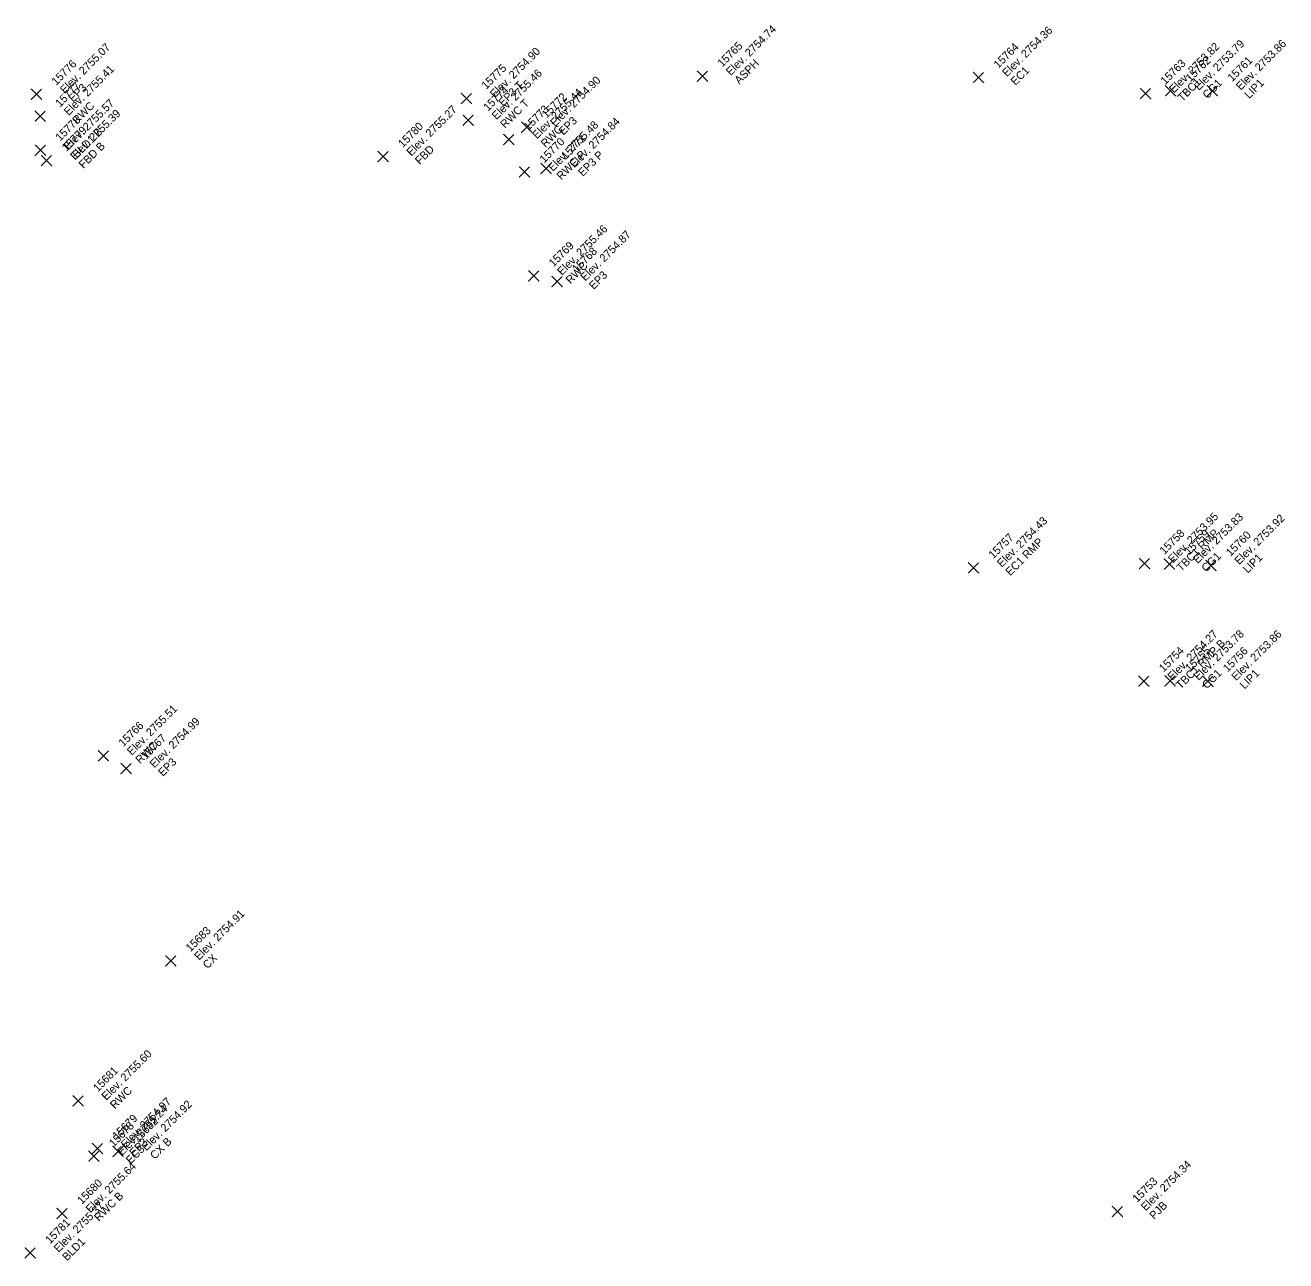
# Model space of a CAD drawing. Extents: x 2493999 to 2503109, y 700767 to 706646.
# Drawn here: x 2502227.16 to 2502264.97, y 704078.66 to 704115.72 of the extents above; entities that cross this region are included whole.
import ezdxf

# ---------------------------------------------------------------- set-up
doc = ezdxf.new("R2010")
doc.units = 0
doc.layers.add('ALG_CL_BLUE_Horiz', color=7, linetype='Continuous')
doc.layers.add('DES_SURFACE_Existing-Ground', color=7, linetype='Continuous')

msp = doc.modelspace()

# ---------------------------------------------------------------- linework, layer by layer
at = {"layer": 'ALG_CL_BLUE_Horiz'}
for points in [[(2502247.476, 704114.191), (2502247.326, 704114.341), (2502247.476, 704114.191), (2502247.326, 704114.041), (2502247.476, 704114.191), (2502247.626, 704114.041), (2502247.476, 704114.191), (2502247.626, 704114.341)], [(2502255.76, 704114.155), (2502255.61, 704114.305), (2502255.76, 704114.155), (2502255.61, 704114.005), (2502255.76, 704114.155), (2502255.91, 704114.005), (2502255.76, 704114.155), (2502255.91, 704114.305)], [(2502227.499, 704113.649), (2502227.349, 704113.799), (2502227.499, 704113.649), (2502227.349, 704113.499), (2502227.499, 704113.649), (2502227.649, 704113.499), (2502227.499, 704113.649), (2502227.649, 704113.799)], [(2502240.395, 704113.524), (2502240.245, 704113.674), (2502240.395, 704113.524), (2502240.245, 704113.374), (2502240.395, 704113.524), (2502240.545, 704113.374), (2502240.395, 704113.524), (2502240.545, 704113.674)], [(2502260.767, 704113.667), (2502260.617, 704113.817), (2502260.767, 704113.667), (2502260.617, 704113.517), (2502260.767, 704113.667), (2502260.917, 704113.517), (2502260.767, 704113.667), (2502260.917, 704113.817)], [(2502261.517, 704113.752), (2502261.367, 704113.902), (2502261.517, 704113.752), (2502261.367, 704113.602), (2502261.517, 704113.752), (2502261.667, 704113.602), (2502261.517, 704113.752), (2502261.667, 704113.902)], [(2502262.772, 704113.755), (2502262.622, 704113.905), (2502262.772, 704113.755), (2502262.622, 704113.605), (2502262.772, 704113.755), (2502262.922, 704113.605), (2502262.772, 704113.755), (2502262.922, 704113.905)], [(2502227.614, 704112.994), (2502227.464, 704113.144), (2502227.614, 704112.994), (2502227.464, 704112.844), (2502227.614, 704112.994), (2502227.764, 704112.844), (2502227.614, 704112.994), (2502227.764, 704113.144)], [(2502240.45, 704112.869), (2502240.3, 704113.019), (2502240.45, 704112.869), (2502240.3, 704112.719), (2502240.45, 704112.869), (2502240.6, 704112.719), (2502240.45, 704112.869), (2502240.6, 704113.019)], [(2502242.205, 704112.66), (2502242.055, 704112.81), (2502242.205, 704112.66), (2502242.055, 704112.51), (2502242.205, 704112.66), (2502242.355, 704112.51), (2502242.205, 704112.66), (2502242.355, 704112.81)], [(2502227.616, 704111.968), (2502227.466, 704112.118), (2502227.616, 704111.968), (2502227.466, 704111.818), (2502227.616, 704111.968), (2502227.766, 704111.818), (2502227.616, 704111.968), (2502227.766, 704112.118)], [(2502241.664, 704112.292), (2502241.514, 704112.442), (2502241.664, 704112.292), (2502241.514, 704112.142), (2502241.664, 704112.292), (2502241.814, 704112.142), (2502241.664, 704112.292), (2502241.814, 704112.442)], [(2502227.805, 704111.661), (2502227.655, 704111.811), (2502227.805, 704111.661), (2502227.655, 704111.511), (2502227.805, 704111.661), (2502227.955, 704111.511), (2502227.805, 704111.661), (2502227.955, 704111.811)], [(2502237.896, 704111.779), (2502237.746, 704111.929), (2502237.896, 704111.779), (2502237.746, 704111.629), (2502237.896, 704111.779), (2502238.046, 704111.629), (2502237.896, 704111.779), (2502238.046, 704111.929)], [(2502242.139, 704111.318), (2502241.989, 704111.468), (2502242.139, 704111.318), (2502241.989, 704111.168), (2502242.139, 704111.318), (2502242.289, 704111.168), (2502242.139, 704111.318), (2502242.289, 704111.468)], [(2502242.786, 704111.42), (2502242.636, 704111.57), (2502242.786, 704111.42), (2502242.636, 704111.27), (2502242.786, 704111.42), (2502242.936, 704111.27), (2502242.786, 704111.42), (2502242.936, 704111.57)], [(2502242.415, 704108.2), (2502242.265, 704108.35), (2502242.415, 704108.2), (2502242.265, 704108.05), (2502242.415, 704108.2), (2502242.565, 704108.05), (2502242.415, 704108.2), (2502242.565, 704108.35)], [(2502243.114, 704108.03), (2502242.964, 704108.18), (2502243.114, 704108.03), (2502242.964, 704107.88), (2502243.114, 704108.03), (2502243.264, 704107.88), (2502243.114, 704108.03), (2502243.264, 704108.18)], [(2502260.736, 704099.574), (2502260.586, 704099.724), (2502260.736, 704099.574), (2502260.586, 704099.424), (2502260.736, 704099.574), (2502260.886, 704099.424), (2502260.736, 704099.574), (2502260.886, 704099.724)], [(2502261.483, 704099.559), (2502261.333, 704099.709), (2502261.483, 704099.559), (2502261.333, 704099.409), (2502261.483, 704099.559), (2502261.633, 704099.409), (2502261.483, 704099.559), (2502261.633, 704099.709)], [(2502262.727, 704099.519), (2502262.577, 704099.669), (2502262.727, 704099.519), (2502262.577, 704099.369), (2502262.727, 704099.519), (2502262.877, 704099.369), (2502262.727, 704099.519), (2502262.877, 704099.669)], [(2502255.607, 704099.446), (2502255.457, 704099.596), (2502255.607, 704099.446), (2502255.457, 704099.296), (2502255.607, 704099.446), (2502255.757, 704099.296), (2502255.607, 704099.446), (2502255.757, 704099.596)], [(2502260.718, 704096.048), (2502260.568, 704096.198), (2502260.718, 704096.048), (2502260.568, 704095.898), (2502260.718, 704096.048), (2502260.868, 704095.898), (2502260.718, 704096.048), (2502260.868, 704096.198)], [(2502261.504, 704096.053), (2502261.354, 704096.203), (2502261.504, 704096.053), (2502261.354, 704095.903), (2502261.504, 704096.053), (2502261.654, 704095.903), (2502261.504, 704096.053), (2502261.654, 704096.203)], [(2502262.636, 704096.046), (2502262.486, 704096.196), (2502262.636, 704096.046), (2502262.486, 704095.896), (2502262.636, 704096.046), (2502262.786, 704095.896), (2502262.636, 704096.046), (2502262.786, 704096.196)], [(2502229.509, 704093.807), (2502229.359, 704093.957), (2502229.509, 704093.807), (2502229.359, 704093.657), (2502229.509, 704093.807), (2502229.659, 704093.657), (2502229.509, 704093.807), (2502229.659, 704093.957)], [(2502230.188, 704093.426), (2502230.038, 704093.576), (2502230.188, 704093.426), (2502230.038, 704093.276), (2502230.188, 704093.426), (2502230.338, 704093.276), (2502230.188, 704093.426), (2502230.338, 704093.576)], [(2502231.527, 704087.658), (2502231.377, 704087.808), (2502231.527, 704087.658), (2502231.377, 704087.508), (2502231.527, 704087.658), (2502231.677, 704087.508), (2502231.527, 704087.658), (2502231.677, 704087.808)], [(2502228.746, 704083.457), (2502228.596, 704083.607), (2502228.746, 704083.457), (2502228.596, 704083.307), (2502228.746, 704083.457), (2502228.896, 704083.307), (2502228.746, 704083.457), (2502228.896, 704083.607)], [(2502229.221, 704081.802), (2502229.071, 704081.952), (2502229.221, 704081.802), (2502229.071, 704081.652), (2502229.221, 704081.802), (2502229.371, 704081.652), (2502229.221, 704081.802), (2502229.371, 704081.952)], [(2502229.326, 704082.025), (2502229.176, 704082.175), (2502229.326, 704082.025), (2502229.176, 704081.875), (2502229.326, 704082.025), (2502229.476, 704081.875), (2502229.326, 704082.025), (2502229.476, 704082.175)], [(2502229.946, 704081.943), (2502229.796, 704082.093), (2502229.946, 704081.943), (2502229.796, 704081.793), (2502229.946, 704081.943), (2502230.096, 704081.793), (2502229.946, 704081.943), (2502230.096, 704082.093)], [(2502228.27, 704080.084), (2502228.12, 704080.234), (2502228.27, 704080.084), (2502228.12, 704079.934), (2502228.27, 704080.084), (2502228.42, 704079.934), (2502228.27, 704080.084), (2502228.42, 704080.234)], [(2502259.923, 704080.14), (2502259.773, 704080.29), (2502259.923, 704080.14), (2502259.773, 704079.99), (2502259.923, 704080.14), (2502260.073, 704079.99), (2502259.923, 704080.14), (2502260.073, 704080.29)], [(2502227.312, 704078.898), (2502227.162, 704079.048), (2502227.312, 704078.898), (2502227.162, 704078.748), (2502227.312, 704078.898), (2502227.462, 704078.748), (2502227.312, 704078.898), (2502227.462, 704079.048)]]:
    msp.add_lwpolyline(points, dxfattribs=at)

# ---------------------------------------------------------------- texts
at = {"layer": 'DES_SURFACE_Existing-Ground'}
for s, p in [('Elev. 2754.74', (2502248.325, 704114.191)), ('Elev. 2754.36', (2502256.609, 704114.155)), ('Elev. 2755.07', (2502228.348, 704113.649)), ('15765', (2502248.07, 704114.446)), ('15764', (2502256.354, 704114.41)), ('Elev. 2753.82', (2502261.616, 704113.667)), ('Elev. 2753.79', (2502262.366, 704113.752)), ('Elev. 2753.86', (2502263.621, 704113.755)), ('Elev. 2754.90', (2502241.244, 704113.524)), ('15762', (2502262.111, 704114.007)), ('15761', (2502263.366, 704114.01)), ('15776', (2502228.093, 704113.904)), ('Elev. 2755.41', (2502228.463, 704112.994)), ('15775', (2502240.989, 704113.779)), ('Elev. 2755.46', (2502241.299, 704112.869)), ('ASPH', (2502248.579, 704113.936)), ('EC1', (2502256.863, 704113.9)), ('15763', (2502261.361, 704113.922)), ('15777', (2502228.208, 704113.249)), ('EP3 T', (2502241.498, 704113.269)), ('Elev. 2754.90', (2502243.054, 704112.66)), ('TBC1', (2502261.87, 704113.412)), ('CG1', (2502262.62, 704113.497)), ('LIP1', (2502263.875, 704113.5)), ('EP3', (2502228.602, 704113.394)), ('15774', (2502241.044, 704113.124)), ('Elev. 2755.44', (2502242.513, 704112.292)), ('15772', (2502242.799, 704112.915)), ('Elev. 2755.57', (2502228.465, 704111.968)), ('RWC', (2502228.717, 704112.739)), ('Elev. 2755.27', (2502238.745, 704111.779)), ('RWC T', (2502241.553, 704112.614)), ('15773', (2502242.258, 704112.547)), ('15778', (2502228.21, 704112.223)), ('Elev. 2755.39', (2502228.654, 704111.661)), ('EP3', (2502243.308, 704112.405)), ('Elev. 2754.84', (2502243.635, 704111.42)), ('15779', (2502228.399, 704111.916)), ('BLD1 B', (2502228.719, 704111.713)), ('15780', (2502238.49, 704112.034)), ('RWC', (2502242.767, 704112.037)), ('Elev. 2755.48', (2502242.988, 704111.318)), ('FBD B', (2502228.908, 704111.406)), ('FBD', (2502238.999, 704111.524)), ('15770', (2502242.733, 704111.573)), ('15771', (2502243.38, 704111.675)), ('RWC P', (2502243.242, 704111.063)), ('EP3 P', (2502243.889, 704111.165)), ('Elev. 2755.46', (2502243.264, 704108.2)), ('Elev. 2754.87', (2502243.963, 704108.03)), ('15769', (2502243.009, 704108.455)), ('15768', (2502243.708, 704108.285)), ('RWC', (2502243.518, 704107.945)), ('EP3', (2502244.217, 704107.775)), ('Elev. 2754.43', (2502256.456, 704099.446)), ('Elev. 2753.95', (2502261.585, 704099.574)), ('Elev. 2753.83', (2502262.332, 704099.559)), ('Elev. 2753.92', (2502263.576, 704099.519)), ('15757', (2502256.201, 704099.701)), ('15758', (2502261.33, 704099.829)), ('TBC1 RMP', (2502261.839, 704099.319)), ('15759', (2502262.077, 704099.814)), ('15760', (2502263.321, 704099.774)), ('EC1 RMP', (2502256.71, 704099.191)), ('CG1', (2502262.586, 704099.304)), ('LIP1', (2502263.83, 704099.264)), ('Elev. 2754.27', (2502261.567, 704096.048)), ('Elev. 2753.78', (2502262.353, 704096.053)), ('Elev. 2753.86', (2502263.485, 704096.046)), ('15754', (2502261.312, 704096.303)), ('TBC1 RMP B', (2502261.821, 704095.793)), ('15755', (2502262.098, 704096.308)), ('15756', (2502263.23, 704096.301)), ('CG1', (2502262.607, 704095.798)), ('LIP1', (2502263.739, 704095.791)), ('Elev. 2755.51', (2502230.358, 704093.807)), ('15766', (2502230.103, 704094.062)), ('Elev. 2754.99', (2502231.037, 704093.426)), ('15767', (2502230.782, 704093.681)), ('RWC', (2502230.612, 704093.552)), ('EP3', (2502231.291, 704093.171)), ('Elev. 2754.91', (2502232.376, 704087.658)), ('15683', (2502232.121, 704087.913)), ('CX', (2502232.63, 704087.403)), ('Elev. 2755.60', (2502229.595, 704083.457)), ('15681', (2502229.34, 704083.712)), ('RWC', (2502229.849, 704083.202)), ('Elev. 2754.97', (2502230.175, 704082.025)), ('Elev. 2754.92', (2502230.795, 704081.943)), ('15679', (2502229.92, 704082.28)), ('Elev. 2755.24', (2502230.07, 704081.802)), ('15678', (2502229.815, 704082.057)), ('15682', (2502230.54, 704082.198)), ('EP3', (2502230.429, 704081.77)), ('CX B', (2502231.049, 704081.688)), ('EC3', (2502230.324, 704081.547)), ('Elev. 2755.64', (2502229.119, 704080.084)), ('Elev. 2754.34', (2502260.772, 704080.14)), ('15680', (2502228.864, 704080.339)), ('15753', (2502260.517, 704080.395)), ('RWC B', (2502229.373, 704079.829)), ('Elev. 2755.37', (2502228.161, 704078.898)), ('PJB', (2502261.026, 704079.885)), ('15781', (2502227.906, 704079.153)), ('BLD1', (2502228.415, 704078.643))]:
    msp.add_text(s, height=0.24, rotation=45, dxfattribs=at).set_placement(p)

doc.saveas('drawing.dxf')
